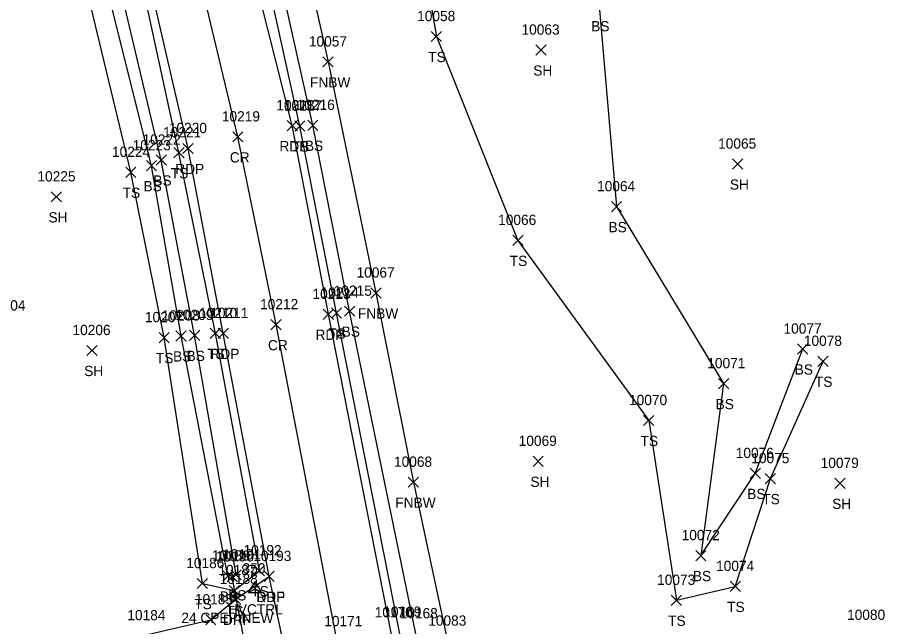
# Model space of a CAD drawing. Extents: x 1475671 to 1477951, y 592661 to 593821.
# Drawn here: x 1476843.4 to 1477012.7, y 592838.1 to 592957 of the extents above; entities that cross this region are included whole.
import ezdxf

# ---------------------------------------------------------------- set-up
doc = ezdxf.new("R2010")
doc.units = 0
for name, color, linetype in [('C_A', 7, 'Continuous'), ('C_I', 7, 'Continuous'), ('CPSM', 7, 'Continuous'), ('D_A', 7, 'Continuous'), ('D_C', 7, 'Continuous'), ('D_I', 7, 'Continuous'), ('D_TIC', 7, 'Continuous'), ('DCP', 7, 'Continuous'), ('L_A', 7, 'Continuous'), ('L_I', 7, 'Continuous'), ('L_TIC', 7, 'Continuous'), ('LELB', 7, 'Continuous'), ('LFNC', 7, 'Continuous'), ('P_A', 7, 'Continuous'), ('P_I', 7, 'Continuous'), ('P_TIC', 7, 'Continuous'), ('PET', 7, 'Continuous'), ('PRC', 7, 'Continuous'), ('R_A', 7, 'Continuous'), ('R_I', 7, 'Continuous'), ('R_TIC', 7, 'Continuous'), ('RDF', 7, 'Continuous')]:
    doc.layers.add(name, color=color, linetype=linetype)

msp = doc.modelspace()

# ---------------------------------------------------------------- linework, layer by layer
at = {"layer": 'CPSM'}
for p, q in [((1476888.51, 592844.72), (1476889.76, 592846.89)), ((1476891.01, 592844.72), (1476889.76, 592846.89)), ((1476889.76, 592845.44), (1476889.76, 592846.89)), ((1476888.51, 592844.72), (1476889.76, 592845.44)), ((1476889.76, 592845.44), (1476889.76, 592845.44)), ((1476889.76, 592845.44), (1476891.01, 592844.72)), ((1476888.51, 592844.72), (1476891.01, 592844.72))]:
    msp.add_line(p, q, dxfattribs=at)
at = {"layer": 'D_TIC'}
for points in [[(1476884.32, 592846.78), (1476886.32, 592848.78)], [(1476886.32, 592846.78), (1476884.32, 592848.78)]]:
    msp.add_lwpolyline(points, dxfattribs=at)
at = {"layer": 'DCP'}
msp.add_lwpolyline([(1476891.06, 592817.38), (1476885.32, 592847.78)], dxfattribs=at)
at = {"layer": 'L_TIC'}
for points in [[(1476924.15, 592952.22), (1476926.15, 592954.22)], [(1476926.15, 592952.22), (1476924.15, 592954.22)], [(1476944.57, 592949.58), (1476946.57, 592951.58)], [(1476946.57, 592949.58), (1476944.57, 592951.58)], [(1476903.01, 592947.27), (1476905.01, 592949.27)], [(1476905.01, 592947.27), (1476903.01, 592949.27)], [(1476897.49, 592934.73), (1476899.49, 592936.73)], [(1476899.49, 592934.73), (1476897.49, 592936.73)], [(1476900.04, 592934.89), (1476902.04, 592936.89)], [(1476902.04, 592934.89), (1476900.04, 592936.89)], [(1476873.91, 592929.53), (1476875.91, 592931.53)], [(1476875.91, 592929.53), (1476873.91, 592931.53)], [(1476870.46, 592928.11), (1476872.46, 592930.11)], [(1476872.46, 592928.11), (1476870.46, 592930.11)], [(1476868.54, 592927.01), (1476870.54, 592929.01)], [(1476870.54, 592927.01), (1476868.54, 592929.01)], [(1476982.95, 592927.33), (1476984.95, 592929.33)], [(1476984.95, 592927.33), (1476982.95, 592929.33)], [(1476864.51, 592925.72), (1476866.51, 592927.72)], [(1476866.51, 592925.72), (1476864.51, 592927.72)], [(1476849.95, 592920.93), (1476851.95, 592922.93)], [(1476851.95, 592920.93), (1476849.95, 592922.93)], [(1476959.31, 592919.02), (1476961.31, 592921.02)], [(1476961.31, 592919.02), (1476959.31, 592921.02)], [(1476940.06, 592912.44), (1476942.06, 592914.44)], [(1476942.06, 592912.44), (1476940.06, 592914.44)], [(1476912.36, 592902.17), (1476914.36, 592904.17)], [(1476914.36, 592902.17), (1476912.36, 592904.17)], [(1476904.66, 592898.26), (1476906.66, 592900.26)], [(1476906.66, 592898.26), (1476904.66, 592900.26)], [(1476907.22, 592898.62), (1476909.22, 592900.62)], [(1476909.22, 592898.62), (1476907.22, 592900.62)], [(1476876.95, 592893.89), (1476878.95, 592895.89)], [(1476878.95, 592893.89), (1476876.95, 592895.89)], [(1476881.01, 592894.28), (1476883.01, 592896.28)], [(1476883.01, 592894.28), (1476881.01, 592896.28)], [(1476871.01, 592893.47), (1476873.01, 592895.47)], [(1476873.01, 592893.47), (1476871.01, 592895.47)], [(1476874.31, 592893.79), (1476876.31, 592895.79)], [(1476876.31, 592893.79), (1476874.31, 592895.79)], [(1476856.92, 592890.95), (1476858.92, 592892.95)], [(1476858.92, 592890.95), (1476856.92, 592892.95)], [(1476995.65, 592891.24), (1476997.65, 592893.24)], [(1476997.65, 592891.24), (1476995.65, 592893.24)], [(1476999.63, 592888.85), (1477001.63, 592890.85)], [(1477001.63, 592888.85), (1476999.63, 592890.85)], [(1476980.21, 592884.48), (1476982.21, 592886.48)], [(1476982.21, 592884.48), (1476980.21, 592886.48)], [(1476965.6, 592877.29), (1476967.6, 592879.29)], [(1476967.6, 592877.29), (1476965.6, 592879.29)], [(1476944.02, 592869.33), (1476946.02, 592871.33)], [(1476946.02, 592869.33), (1476944.02, 592871.33)], [(1476986.39, 592866.96), (1476988.39, 592868.96)], [(1476988.39, 592866.96), (1476986.39, 592868.96)], [(1476919.67, 592865.25), (1476921.67, 592867.25)], [(1476921.67, 592865.25), (1476919.67, 592867.25)], [(1476989.36, 592865.95), (1476991.36, 592867.95)], [(1476991.36, 592865.95), (1476989.36, 592867.95)], [(1477002.92, 592865.02), (1477004.92, 592867.02)], [(1477004.92, 592865.02), (1477002.92, 592867.02)], [(1476975.78, 592850.93), (1476977.78, 592852.93)], [(1476977.78, 592850.93), (1476975.78, 592852.93)], [(1476883.44, 592846.94), (1476885.44, 592848.94)], [(1476885.44, 592846.94), (1476883.44, 592848.94)], [(1476883.44, 592846.94), (1476885.44, 592848.94)], [(1476885.44, 592846.94), (1476883.44, 592848.94)], [(1476885.05, 592847.17), (1476887.05, 592849.17)], [(1476887.05, 592847.17), (1476885.05, 592849.17)], [(1476889.61, 592847.98), (1476891.61, 592849.98)], [(1476891.61, 592847.98), (1476889.61, 592849.98)], [(1476878.49, 592845.47), (1476880.49, 592847.47)], [(1476880.49, 592845.47), (1476878.49, 592847.47)], [(1476878.49, 592845.47), (1476880.49, 592847.47)], [(1476880.49, 592845.47), (1476878.49, 592847.47)], [(1476982.5, 592844.91), (1476984.5, 592846.91)], [(1476984.5, 592844.91), (1476982.5, 592846.91)], [(1476884.7, 592844.11), (1476886.7, 592846.11)], [(1476886.7, 592844.11), (1476884.7, 592846.11)], [(1476970.99, 592842.21), (1476972.99, 592844.21)], [(1476972.99, 592842.21), (1476970.99, 592844.21)]]:
    msp.add_lwpolyline(points, dxfattribs=at)
at = {"layer": 'LELB'}
for points in [[(1476945.37, 592716.49), (1476943.84, 592716.05), (1476935.5, 592756.29), (1476927.52, 592796.97), (1476921.14, 592836.68), (1476908.22, 592899.62), (1476901.04, 592935.89), (1476890.97, 592981.04), (1476883.12, 593008.63), (1476873.18, 593048.38)], [(1476947.68, 592723.33), (1476948.72, 592716.37), (1476942.58, 592713.1), (1476940.5, 592717.38), (1476933.16, 592755.58), (1476925.3, 592796.65), (1476917.94, 592836.99), (1476905.66, 592899.26), (1476898.49, 592935.73), (1476888.52, 592980.9), (1476879.22, 593010.04), (1476868.24, 593047.6)], [(1476952.72, 593027.76), (1476936.48, 593010.35), (1476917.23, 592997.95), (1476925.15, 592953.22), (1476941.06, 592913.44), (1476966.6, 592878.29), (1476971.99, 592843.21), (1476983.5, 592845.91), (1476990.36, 592866.95), (1477000.63, 592889.85)], [(1476884.44, 592847.94), (1476886.05, 592848.17), (1476877.95, 592894.89), (1476871.46, 592929.11), (1476860.55, 592974.99), (1476855.78, 592990.95), (1476849.63, 593004.41), (1476844.42, 593012.56)], [(1476879.49, 592846.47), (1476885.7, 592845.11), (1476890.61, 592848.98), (1476882.01, 592895.28), (1476874.91, 592930.53), (1476865.07, 592975.92), (1476858.93, 592991.8), (1476852.6, 593006.17)], [(1476879.49, 592846.47), (1476872.01, 592894.47), (1476865.51, 592926.72), (1476854.26, 592973.53), (1476850.02, 592989.43), (1476843.57, 593001.16)], [(1476884.44, 592847.94), (1476875.31, 592894.79), (1476869.54, 592928.01), (1476857.87, 592974.58), (1476852.83, 592990.03), (1476846.68, 593002.44)], [(1476960.56, 592988.77), (1476956.93, 592959.23), (1476960.31, 592920.02), (1476981.21, 592885.48), (1476976.78, 592851.93), (1476987.39, 592867.96), (1476996.65, 592892.24)]]:
    msp.add_lwpolyline(points, dxfattribs=at)
at = {"layer": 'LFNC'}
msp.add_lwpolyline([(1476884.45, 593049.97), (1476888.66, 593028.15), (1476895.68, 592985.33), (1476904.01, 592948.27), (1476913.36, 592903.17), (1476920.67, 592866.25), (1476927.31, 592835.25), (1476934.4, 592801.93), (1476940.69, 592763.21), (1476947.68, 592723.33)], dxfattribs=at)
at = {"layer": 'P_TIC'}
for points in [[(1476896.02, 592934.82), (1476898.02, 592936.82)], [(1476898.02, 592934.82), (1476896.02, 592936.82)], [(1476885.39, 592932.64), (1476887.39, 592934.64)], [(1476887.39, 592932.64), (1476885.39, 592934.64)], [(1476875.69, 592930.37), (1476877.69, 592932.37)], [(1476877.69, 592930.37), (1476875.69, 592932.37)], [(1476903.07, 592898.01), (1476905.07, 592900.01)], [(1476905.07, 592898.01), (1476903.07, 592900.01)], [(1476892.85, 592895.99), (1476894.85, 592897.99)], [(1476894.85, 592895.99), (1476892.85, 592897.99)], [(1476882.56, 592894.28), (1476884.56, 592896.28)], [(1476884.56, 592894.28), (1476882.56, 592896.28)], [(1476891.51, 592846.86), (1476893.51, 592848.86)], [(1476893.51, 592846.86), (1476891.51, 592848.86)]]:
    msp.add_lwpolyline(points, dxfattribs=at)
at = {"layer": 'PET'}
for points in [[(1476948.05, 592670.97), (1476946.44, 592678.68), (1476938.73, 592716.33), (1476931.28, 592754.87), (1476923.71, 592796.39), (1476916.31, 592836.87), (1476904.07, 592899.01), (1476897.02, 592935.82), (1476885.79, 592980.24), (1476877.69, 593009.63), (1476865.86, 593046.37), (1476861.23, 593059.8), (1476852.05, 593085.53)], [(1476926.72, 592670.85), (1476919.07, 592710.56), (1476910.29, 592754.48), (1476903.69, 592790.26), (1476898.6, 592819.47), (1476892.51, 592847.86), (1476883.56, 592895.28), (1476876.69, 592931.37), (1476866.39, 592975.94)]]:
    msp.add_lwpolyline(points, dxfattribs=at)
at = {"layer": 'PRC'}
msp.add_lwpolyline([(1476936.41, 592672.33), (1476928.58, 592713.02), (1476920.34, 592755.64), (1476913.25, 592793.06), (1476905.79, 592835.15), (1476893.85, 592896.99), (1476886.39, 592933.64), (1476875.73, 592978.34), (1476865.02, 593017.01), (1476853.41, 593046.52), (1476843.49, 593055.1), (1476828.74, 593067.47), (1476810.85, 593077.22), (1476783.7, 593084.94)], dxfattribs=at)
at = {"layer": 'R_TIC'}
for points in [[(1476891.51, 592846.86), (1476893.51, 592848.86)], [(1476893.51, 592846.86), (1476891.51, 592848.86)], [(1476884.95, 592842.39), (1476886.95, 592844.39)], [(1476886.95, 592842.39), (1476884.95, 592844.39)], [(1476880.12, 592838.41), (1476882.12, 592840.41)], [(1476882.12, 592838.41), (1476880.12, 592840.41)]]:
    msp.add_lwpolyline(points, dxfattribs=at)
at = {"layer": 'RDF'}
msp.add_lwpolyline([(1476898.6, 592819.47), (1476894.02, 592820.25), (1476889.6, 592819.55), (1476870.15, 592820.4), (1476867.93, 592836.31), (1476881.12, 592839.41), (1476885.95, 592843.39), (1476892.51, 592847.86)], dxfattribs=at)

# ---------------------------------------------------------------- texts
at = {"layer": 'C_A'}
msp.add_text('HVCTRL', height=2, dxfattribs=at).set_placement((1476884.46, 592840.44))
at = {"layer": 'C_I'}
msp.add_text('350', height=2, dxfattribs=at).set_placement((1476887.31, 592848.44))
at = {"layer": 'D_A'}
msp.add_text('P', height=2, dxfattribs=at).set_placement((1476884.7, 592842.78))
at = {"layer": 'D_C'}
msp.add_text('24 CPEP NEW', height=2, dxfattribs=at).set_placement((1476875.37, 592838.78))
at = {"layer": 'D_I'}
msp.add_text('10190', height=2, dxfattribs=at).set_placement((1476882.13, 592850.78))
at = {"layer": 'L_A'}
for s, p in [('BS', (1476955.37, 592954.23)), ('TS', (1476923.56, 592948.22)), ('SH', (1476944.06, 592945.58)), ('FNBW', (1476900.49, 592943.27)), ('TS', (1476896.9, 592930.73)), ('BS', (1476899.48, 592930.89)), ('TS', (1476873.32, 592925.53)), ('BS', (1476867.98, 592923.01)), ('BS', (1476869.9, 592924.11)), ('SH', (1476982.44, 592923.33)), ('TS', (1476863.92, 592921.72)), ('SH', (1476849.44, 592916.93)), ('BS', (1476958.75, 592915.02)), ('TS', (1476939.47, 592908.44)), ('FNBW', (1476909.83, 592898.17)), ('TS', (1476904.07, 592894.26)), ('BS', (1476906.66, 592894.62)), ('TS', (1476870.41, 592889.47)), ('BS', (1476873.75, 592889.79)), ('BS', (1476876.39, 592889.89)), ('TS', (1476880.42, 592890.28)), ('BS', (1476995.09, 592887.24)), ('SH', (1476856.41, 592886.95)), ('TS', (1476999.04, 592884.85)), ('BS', (1476979.65, 592880.48)), ('TS', (1476965.01, 592873.29)), ('SH', (1476943.51, 592865.33)), ('BS', (1476985.83, 592862.96)), ('TS', (1476988.77, 592861.95)), ('FNBW', (1476917.14, 592861.25)), ('SH', (1477002.41, 592861.02)), ('BS', (1476975.22, 592846.93)), ('BS', (1476884.49, 592843.17)), ('TS', (1476889.02, 592843.98)), ('TS', (1476877.9, 592841.47)), ('TS', (1476877.9, 592841.47)), ('BS', (1476882.88, 592842.94)), ('BS', (1476882.88, 592842.94)), ('TS', (1476884.11, 592840.11)), ('TS', (1476981.91, 592840.91)), ('TS', (1476970.4, 592838.21))]:
    msp.add_text(s, height=2, dxfattribs=at).set_placement(p)
at = {"layer": 'L_I'}
for s, p in [('10058', (1476921.4, 592956.22)), ('10063', (1476941.77, 592953.58)), ('10057', (1476900.27, 592951.27)), ('10217', (1476895.39, 592938.73)), ('10216', (1476897.88, 592938.89)), ('10221', (1476871.8, 592933.53)), ('10222', (1476867.79, 592932.11)), ('10065', (1476980.15, 592931.33)), ('10224', (1476861.84, 592929.72)), ('10223', (1476865.87, 592931.01)), ('10225', (1476847.28, 592924.93)), ('10064', (1476956.52, 592923.02)), ('10066', (1476937.21, 592916.44)), ('10067', (1476909.57, 592906.17)), ('10215', (1476905.12, 592902.62)), ('10214', (1476902.56, 592902.26)), ('10204', (1476837.51, 592899.75)), ('10207', (1476868.26, 592897.47)), ('10208', (1476871.56, 592897.79)), ('10209', (1476874.19, 592897.89)), ('10210', (1476878.83, 592898.28)), ('10206', (1476854.12, 592894.95)), ('10077', (1476992.91, 592895.24)), ('10078', (1476996.88, 592892.85)), ('10071', (1476978.03, 592888.48)), ('10070', (1476962.76, 592881.29)), ('10069', (1476941.22, 592873.33)), ('10076', (1476983.59, 592870.96)), ('10068', (1476916.88, 592869.25)), ('10075', (1476986.62, 592869.95)), ('10079', (1477000.16, 592869.02)), ('10072', (1476973.03, 592854.93)), ('10192', (1476887.51, 592851.98)), ('10189', (1476881.33, 592850.94)), ('10189', (1476881.33, 592850.94)), ('10191', (1476883.51, 592851.17)), ('10186', (1476876.33, 592849.47)), ('10186', (1476876.33, 592849.47)), ('10074', (1476979.75, 592848.91)), ('10187', (1476882.6, 592848.11)), ('10073', (1476968.24, 592846.21)), ('10169', (1476914.79, 592839.99)), ('10168', (1476917.99, 592839.68)), ('10083', (1476923.56, 592838.25)), ('10083', (1476923.56, 592838.25)), ('10080', (1477005.32, 592839.38))]:
    msp.add_text(s, height=2, dxfattribs=at).set_placement(p)
at = {"layer": 'P_A'}
for s, p in [('RDP', (1476894.51, 592930.82)), ('CR', (1476884.83, 592928.64)), ('RDP', (1476874.18, 592926.37)), ('RDP', (1476901.56, 592894.01)), ('CR', (1476892.28, 592891.99)), ('RDP', (1476881.05, 592890.28)), ('RDP', (1476890, 592842.86))]:
    msp.add_text(s, height=2, dxfattribs=at).set_placement(p)
at = {"layer": 'P_I'}
for s, p in [('10218', (1476893.92, 592938.82)), ('10219', (1476883.28, 592936.64)), ('10220', (1476872.93, 592934.37)), ('10213', (1476900.97, 592902.01)), ('10212', (1476890.74, 592899.99)), ('10211', (1476881.02, 592898.28)), ('10193', (1476889.41, 592850.86)), ('10170', (1476913.12, 592839.87)), ('10171', (1476903.26, 592838.15))]:
    msp.add_text(s, height=2, dxfattribs=at).set_placement(p)
at = {"layer": 'R_A'}
for p in [(1476890.04, 592842.86), (1476883.48, 592838.39)]:
    msp.add_text('DRF', height=2, dxfattribs=at).set_placement(p)
at = {"layer": 'R_I'}
for s, p in [('10193', (1476889.41, 592850.86)), ('10188', (1476882.85, 592846.39)), ('10185', (1476878.02, 592842.41)), ('10184', (1476864.83, 592839.31))]:
    msp.add_text(s, height=2, dxfattribs=at).set_placement(p)

doc.saveas('drawing.dxf')
